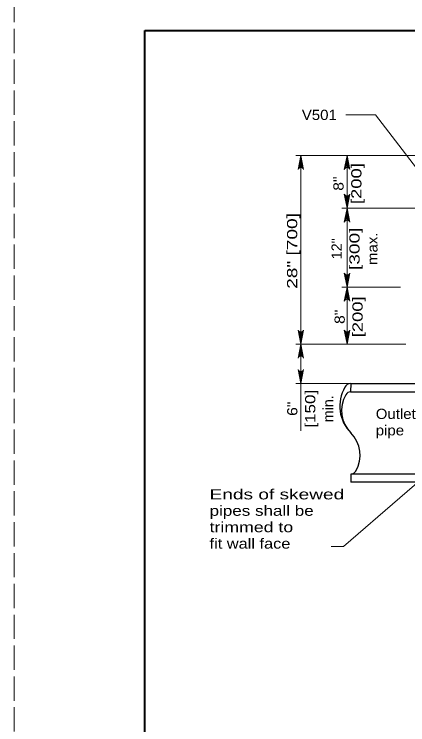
# Model space of a CAD drawing. Extents: x 758.3 to 792.3, y 849.7 to 893.7.
# Drawn here: x 758.32 to 764.35, y 860.56 to 871.44 of the extents above; entities that cross this region are included whole.
import ezdxf
from ezdxf.enums import TextEntityAlignment as Align

# ---------------------------------------------------------------- set-up
doc = ezdxf.new("R2010")
doc.units = 0
doc.header["$LTSCALE"] = 0.062
doc.linetypes.add('LONG_DASHED', pattern=[7.5, 6, -1.5])
doc.layers.add('1', color=7, linetype='Continuous', lineweight=13)

msp = doc.modelspace()

# ---------------------------------------------------------------- linework, layer by layer
at = {"layer": '1', "lineweight": 25}
for p, q in [((760.3205, 871.18817), (791.8205, 871.18817)), ((763.47508, 865.78567), (763.47333, 865.65958)), ((763.47508, 865.78567), (765.19, 865.78567)), ((763.47333, 865.65958), (765.08925, 865.65958)), ((765.19, 864.27392), (763.47667, 864.27392))]:
    msp.add_line(p, q, dxfattribs=at)
at = {"layer": '1'}
for p, q in [((764.49067, 869.27742), (762.63192, 869.27742)), ((762.68067, 869.08125), (762.71058, 869.27742)), ((762.69317, 869.08867), (762.71058, 869.27742)), ((762.71058, 869.09208), (762.71058, 869.27742)), ((762.72433, 869.09008), (762.71058, 869.27742)), ((762.73775, 869.08358), (762.71058, 869.27742)), ((762.71058, 865.06275), (762.71058, 869.27742)), ((763.38867, 869.08125), (763.41858, 869.27742)), ((763.40117, 869.08867), (763.41858, 869.27742)), ((763.41858, 868.96492), (763.41858, 869.27742)), ((763.41858, 869.09208), (763.41858, 869.27742)), ((763.43233, 869.09008), (763.41858, 869.27742)), ((763.44575, 869.08358), (763.41858, 869.27742)), ((763.41858, 868.47125), (763.41858, 868.96492)), ((763.3915, 868.66517), (763.41858, 868.47125)), ((763.40492, 868.65858), (763.41858, 868.47125)), ((763.44858, 868.66742), (763.41858, 868.47125)), ((763.436, 868.66), (763.41858, 868.47125)), ((763.41858, 868.65658), (763.41858, 868.47125)), ((765.06675, 868.47125), (763.33992, 868.47125)), ((763.38867, 868.27508), (763.41858, 868.47125)), ((763.40117, 868.2825), (763.41858, 868.47125)), ((763.41858, 868.28592), (763.41858, 868.47125)), ((763.43233, 868.28392), (763.41858, 868.47125)), ((763.44575, 868.27733), (763.41858, 868.47125)), ((763.3915, 867.45583), (763.41858, 867.26192)), ((763.40492, 867.44925), (763.41858, 867.26192)), ((763.44858, 867.45808), (763.41858, 867.26192)), ((763.436, 867.45067), (763.41858, 867.26192)), ((763.41858, 867.44725), (763.41858, 867.26192)), ((764.23942, 867.26192), (763.33992, 867.26192)), ((763.38867, 867.06575), (763.41858, 867.26192)), ((763.40117, 867.07317), (763.41858, 867.26192)), ((763.41858, 867.07658), (763.41858, 867.26192)), ((763.43233, 867.07458), (763.41858, 867.26192)), ((763.44575, 867.06808), (763.41858, 867.26192)), ((762.6835, 866.58425), (762.71058, 866.39033)), ((762.69692, 866.57767), (762.71058, 866.39033)), ((762.74058, 866.5865), (762.71058, 866.39033)), ((762.728, 866.57908), (762.71058, 866.39033)), ((762.71058, 866.57567), (762.71058, 866.39033)), ((763.3915, 866.58425), (763.41858, 866.39033)), ((763.40492, 866.57767), (763.41858, 866.39033)), ((763.44858, 866.5865), (763.41858, 866.39033)), ((763.436, 866.57908), (763.41858, 866.39033)), ((763.41858, 866.57567), (763.41858, 866.39033)), ((764.3165, 866.39033), (762.63192, 866.39033)), ((762.68067, 866.19417), (762.71058, 866.39033)), ((762.69317, 866.20158), (762.71058, 866.39033)), ((762.71058, 866.205), (762.71058, 866.39033)), ((762.72433, 866.203), (762.71058, 866.39033)), ((762.73775, 866.19642), (762.71058, 866.39033)), ((762.6835, 865.97942), (762.71058, 865.78558)), ((762.74058, 865.98175), (762.71058, 865.78558)), ((762.69692, 865.97292), (762.71058, 865.78558)), ((762.728, 865.97433), (762.71058, 865.78558)), ((762.71058, 865.97092), (762.71058, 865.78558)), ((763.4715, 865.78558), (762.63192, 865.78558))]:
    msp.add_line(p, q, dxfattribs=at)
at = {"layer": '1', "linetype": 'LONG_DASHED'}
msp.add_lwpolyline([(758.3205, 849.68817), (792.3205, 849.68817), (792.3205, 871.68817), (758.3205, 871.68817)], close=True, dxfattribs=at)
at = {"layer": '1', "lineweight": 25}
for points in [[(791.8205, 850.18817), (760.3205, 850.18817), (760.3205, 871.18817)], [(765.08925, 864.39992), (763.47667, 864.39992), (763.47667, 864.27392)]]:
    msp.add_lwpolyline(points, dxfattribs=at)
at = {"layer": '1', "lineweight": 40}
msp.add_lwpolyline([(760.3205, 871.18817), (791.8205, 871.18817), (791.8205, 850.18817), (760.3205, 850.18817)], close=True, dxfattribs=at)
at = {"layer": '1'}
for points in [[(764.78783, 868.68458), (763.85467, 869.90025), (763.401, 869.90025)], [(762.66775, 869.06325), (762.71058, 869.27742), (762.75342, 869.06325)], [(763.37575, 869.06325), (763.41858, 869.27742), (763.46142, 869.06325)], [(763.46142, 868.68542), (763.41858, 868.47125), (763.37575, 868.68542)], [(763.37575, 868.25708), (763.41858, 868.47125), (763.46142, 868.25708)], [(763.41858, 866.39033), (763.41858, 867.26192), (763.41858, 868.47125)], [(763.46142, 867.47608), (763.41858, 867.26192), (763.37575, 867.47608)], [(763.37575, 867.04775), (763.41858, 867.26192), (763.46142, 867.04775)], [(762.75342, 866.6045), (762.71058, 866.39033), (762.66775, 866.6045)], [(763.46142, 866.6045), (763.41858, 866.39033), (763.37575, 866.6045)], [(762.66775, 866.17617), (762.71058, 866.39033), (762.75342, 866.17617)], [(762.75342, 865.99975), (762.71058, 865.78558), (762.66775, 865.99975)], [(765.09033, 864.7815), (763.36183, 863.29267), (763.17392, 863.29267)]]:
    msp.add_lwpolyline(points, dxfattribs=at)
for centre, start, end in [((762.71067, 869.04598), 22.08782, 157.91395), ((763.41867, 869.04598), 22.08782, 157.91395), ((763.41857, 868.70271), 202.08782, 337.91395), ((763.41867, 868.23978), 22.08782, 157.91395), ((763.41857, 867.4934), 202.08782, 337.91395), ((763.41867, 867.03047), 22.08782, 157.91395), ((762.71057, 866.6218), 202.08782, 337.91395), ((763.41857, 866.6218), 202.08782, 337.91395), ((762.71067, 866.15887), 22.08782, 157.91395), ((762.71057, 866.01701), 202.08782, 337.91395)]:
    msp.add_arc(centre, 0.04623, start, end, dxfattribs=at)
at = {"layer": '1', "lineweight": 25}
for centre, major_axis, ratio, start_param, end_param in [((763.47668, 865.67664), (0, 0.10904), 0.967314, 0.04919385, 1.06207498), ((763.88668, 865.43982), (-0.57982, 0), 0.999895, 5.75948462, 7.06858347), ((763.4765, 865.56873), (0, 0.09086), 0.967314, 0.01986805, 1.06207498), ((763.81815, 865.37139), (-0.48317, 0), 0.999895, 5.75948462, 7.06858347), ((763.13521, 864.68834), (0.48317, 0), 0.999895, 5.75948462, 7.06858347), ((763.47686, 864.491), (0, -0.09086), 0.967314, 6.28162367, 7.34526029)]:
    msp.add_ellipse(centre, major_axis=major_axis, ratio=ratio, start_param=start_param, end_param=end_param, dxfattribs=at)

# ---------------------------------------------------------------- texts
at = {"layer": '1'}
for s, width, p in [('V501', 1.1, (762.72567, 869.81933)), ('Outlet', 1.1, (763.85817, 865.24342)), ('pipe', 1.1, (763.85817, 864.99225)), ('Ends of skewed', 1.4, (761.31283, 864.01283)), ('pipes shall be', 1.25, (761.31283, 863.76167)), ('trimmed to', 1.3, (761.31283, 863.5105)), ('fit wall face', 1.2, (761.31283, 863.25933))]:
    msp.add_text(s, height=0.156, dxfattribs=dict(at, width=width)).set_placement(p)
for s, width, p in [('[200]', 1.35, (763.63858, 868.84579)), ('8"', 1.15, (763.36458, 868.84571)), ('[300]', 1.4, (763.61042, 867.84821)), ('max.', 1.1, (763.88442, 867.84812)), ('12"', 1.05, (763.33642, 867.84821)), ('[200]', 1.35, (763.657, 866.80696)), ('8"', 1.15, (763.383, 866.80687)), ('[150]', 1.25, (762.93183, 865.39971)), ('min.', 1.05, (763.20583, 865.39979)), ('6"', 1.15, (762.65783, 865.39971))]:
    msp.add_text(s, height=0.156, rotation=90, dxfattribs=dict(at, width=width)).set_placement(p, align=Align.CENTER)
at = {"layer": '1', "width": 1.4}
msp.add_text('28" [700]', height=0.156, rotation=90, dxfattribs=at).set_placement((762.65508, 867.23575))

doc.saveas('drawing.dxf')
